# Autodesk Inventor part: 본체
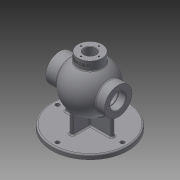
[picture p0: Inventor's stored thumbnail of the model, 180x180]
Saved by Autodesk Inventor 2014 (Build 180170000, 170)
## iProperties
Created: 2020-08
Part Number: 본체
Material: Generic
Document SubType Name: Modeling
Designer: kh
Density: 1 g/cm^3
Appearance: Default
Author: kh
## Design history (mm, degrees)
sketch "Sketch1"
  geometry: C1 r 85 at (0, 0); 1 further point
  constraints: 1 centre point, 1 coincident
  dimensions: "d0" = 170 diameter of C1
extrude "Extrusion1" new body sketch "Sketch1" distance "d1" = 10; taper "d2" = 0 deg
sketch "Sketch2"
  geometry: L1 (85, 10)-(-85, 10) reference; L2 (-85, 0)-(85, 0) reference; L3 (0, 0)-(0, 137.595); L4 (54.192, 85)-(43, 85); L5 (53, 85)-(43, 85); L6 (-43, 85)-(-53, 85); L7 (43, 85)-(-43, 85); A1 r 53 centre (0, 85) between (53, 85) and (-53, 85); A2 r 43 centre (0, 85) between (43, 85) and (-43, 85); 1 further point
  constraints: 10 end point, 4 collinear, 4 point on circle, 2 centre point, 2 coincident, 2 parallel, 2 point on line, 1 midpoint, 1 perpendicular
  dimensions: "d5" = 53 radius of A1; "d7" = 85 distance between parallel lines of L2 L7; "d8" = 43 radius of A2
revolve "Revolution1" sketch "Sketch2" stored, may be unused: angle "d9" = 90 deg
workplane "Work Plane1"
sketch "Sketch3"
  geometry: L1 (85, 10)-(-85, 10) reference; L2 (-85, 0)-(85, 0) reference; L3 (0, 0)-(0, 115.121); C1 r 31 at (0, 85)
  constraints: 2 end point, 1 centre point, 1 perpendicular, 1 point on line
  dimensions: "d11" = 62 diameter of C1; "d12" = 85 distance from line of L2 C1.centre
extrude "Extrusion2" join sketch "Sketch3" stored distance "d13" = 10; taper "d14" = 0 deg
workplane "Work Plane2"
sketch "Sketch4"
  geometry: L1 (0, 0)-(0, 109.575); L2 (-85, 0)-(85, 0) reference; C1 r 31 at (0, 85)
  constraints: 2 end point, 1 centre point, 1 point on line, 1 vertical
  dimensions: "d16" = 62 diameter of C1; "d17" = 85 distance from line of L2 C1.centre
extrude "Extrusion3" join sketch "Sketch4" stored distance "d18" = 10; taper "d19" = 0 deg
workplane "Work Plane3"
sketch "Sketch6"
  geometry: C1 r 27 at (0, 0); 1 further point
  constraints: 1 centre point, 1 coincident
  dimensions: "d24" = 54 diameter of C1
extrude "Extrusion5" join sketch "Sketch6" stored distance "d25" = 10; taper "d26" = 0 deg
sketch "Sketch12"
  geometry: L1 (-52, 4)-(52, 4); L2 (52, 4)-(52, -4); L3 (52, -4)-(-52, -4); L4 (-52, -4)-(-52, 4); L5 (0, 4)-(0, -4); 3 further points
  constraints: 10 end point, 4 midpoint, 2 parallel, 2 perpendicular, 1 coincident, 1 horizontal, 1 horizontal alignment, 1 other
  dimensions: "d36" = 104 distance of L1.start L1.end; "d37" = 8 distance of L1.end L2.end
extrude "Extrusion9" join sketch "Sketch12" stored distance "d38" = 1.75; taper "d39" = 0 deg
sketch "Sketch17"
  geometry: L1 (85, 10)-(-85, 10) reference; L2 (-43, 10)-(-43, 39.933); L3 (43, 10)-(43, 41.466); L4 (0, 0)-(0, 61.704)
  constraints: 6 end point, 2 parallel, 2 point on line, 1 perpendicular
  dimensions: "d44" = 43 distance from line of L2 L4.start; "d45" = 43 distance from line of L3 L4.start
feature "Rib1" dims "d46" = 1, "d47" = 8, "d48" = 0, "d49" = 0, "d50" = 1, "d51" = 1
feature "Rib2" dims "d52" = 1, "d53" = 8, "d54" = 0, "d55" = 0, "d56" = 1, "d57" = 1
sketch "Sketch18"
  geometry: C1 r 27 at (0, 0) reference; 1 further point
hole "Hole1" sketch "Sketch18" at (0, 0) diameter "d58" = 26; stored, may be unused: countersink angle "d62" = 90 deg, drill point angle "d64" = 0 deg; dims "d59" = 6, "d60" = 4, "d61" = 2, "d63" = 50
sketch "Sketch19" dims "d65" = 48
  geometry: L1 (0, 0)-(-24, 0); C1 r 31 at (0, 0) reference; 1 further point
  constraints: 2 end point, 1 coincident, 1 horizontal, 1 horizontal alignment, 2 other
hole "Hole2" sketch "Sketch19" at (-24, 0) diameter "d66" = 3.242; stored, may be unused: countersink angle "d70" = 90 deg, drill point angle "d72" = 118 deg; dims "d67" = 12, "d68" = 4, "d69" = 2, "d71" = 15
pattern_circular "Circular Pattern1" dims angle "d74" = 360 deg
sketch "Sketch20" dims "d76" = 48
  geometry: L1 (0, 0)-(24, 0); A1 r 31 centre (0, 0) between (-30.741, -4) and (-30.741, 4) reference; 1 further point
  constraints: 2 end point, 1 coincident, 1 horizontal, 1 horizontal alignment, 2 other
hole "Hole3" sketch "Sketch20" at (24, 0) diameter "d77" = 3.242; stored, may be unused: countersink angle "d81" = 90 deg, drill point angle "d83" = 118 deg; dims "d78" = 12, "d79" = 4, "d80" = 2, "d82" = 15
pattern_circular "Circular Pattern2" dims angle "d85" = 360 deg
sketch "Sketch21" dims "d87" = 40
  geometry: L1 (0, 0)-(0, 20); C1 r 27 at (0, 0) reference; 1 further point
  constraints: 2 end point, 1 coincident, 1 vertical, 1 vertical alignment, 2 other
hole "Hole4" sketch "Sketch21" at (0, 20) diameter "d88" = 3.242; stored, may be unused: countersink angle "d92" = 90 deg, drill point angle "d94" = 118 deg; dims "d89" = 12, "d90" = 4, "d91" = 2, "d93" = 15
pattern_circular "Circular Pattern3" dims angle "d96" = 360 deg
sketch "Sketch22"
  geometry: L1 (-72.5, 0)-(72.5, 0); L2 (0, -72.5)-(0, 72.5); C1 r 85 at (0, 0) reference; A1 r 72.5 centre (0, 0) between (-72.5, 0) and (72.5, 0); 2 further points
  constraints: 4 end point, 4 point on circle, 2 midpoint, 1 centre point, 1 coincident, 1 horizontal, 1 perpendicular
  dimensions: "d98" = 145 diameter of A1
hole "Hole5" sketch "Sketch22" at (-72.5, 0), (0, -72.5), (72.5, 0), (0, 72.5) diameter "d99" = 9; stored, may be unused: countersink angle "d103" = 90 deg, drill point angle "d105" = 0 deg; dims "d100" = 12, "d101" = 4, "d102" = 2, "d104" = 15
chamfer "Chamfer2" distance "d109" = 1; stored, may be unused: second distance "d110" = 2, angle "d111" = 45 deg
fillet "Fillet1" dims "d115" = 3
fillet "Fillet2" dims "d116" = 3
fillet "Fillet3" dims "d117" = 3
fillet "Fillet4" dims "d118" = 3
fillet "Fillet5" dims "d119" = 3
workplane "Work Plane4"
sketch "Sketch23"
  geometry: L1 (-27, 0)-(27, 0) reference; L2 (-27, -17.714)-(27, -17.714) reference; L3 (-27, 0)-(-27, -17.714) reference; L4 (27, 0)-(27, -17.714) reference; L5 (-20.739, -5.998)-(20.739, -5.998); L6 (20.739, -5.998)-(20.739, -12.002); L7 (20.739, -12.002)-(-20.739, -12.002); L8 (-20.739, -12.002)-(-20.739, -5.998); L9 (-20.739, -5.998)-(20.739, -12.002); 2 further points
  constraints: 2 end point, 1 midpoint, 2 other
  dimensions: "d120" = 27 distance from line of point (0, -9) L3; "d121" = 9 distance from line of point (0, -9) L1
emboss "Emboss1" sketch "Sketch23" dims "d0" = 170, "d122" = 0.5, "d123" = 0
sketch "Sketch25"
  geometry: C1 r 1.621 at (0, -24) reference; C2 r 1.621 at (24, 0) reference; C3 r 1.621 at (0, 24) reference; C4 r 1.621 at (-24, 0) reference; C5 r 31 at (0, 0) reference; C6 r 17.5 at (0, 0); 1 further point
  constraints: 1 centre point, 1 coincident
  dimensions: "d124" = 35 diameter of C6
extrude "Extrusion11" cut sketch "Sketch25" distance "d125" = 16; taper "d126" = 0 deg
sketch "Sketch26"
  geometry: C1 r 17.5 at (0, 0) reference; C2 r 18.5 at (0, 0); 1 further point
  constraints: 1 centre point, 1 coincident
  dimensions: "d127" = 37 diameter of C2
extrude "Extrusion12" cut sketch "Sketch26" distance "d128" = 1.75; taper "d129" = 0 deg
sketch "Sketch27"
  geometry: C1 r 18.5 at (0, 0) reference; C2 r 17.5 at (0, 0); 1 further point
  constraints: 1 centre point, 1 coincident
  dimensions: "d130" = 35 diameter of C2
extrude "Extrusion13" cut sketch "Sketch27" stored distance "d131" = 1.75; taper "d132" = 0 deg
chamfer "Chamfer4" distance "d133" = 1; stored, may be unused: second distance "d134" = 2, angle "d135" = 45 deg
chamfer "Chamfer5" distance "d136" = 1; stored, may be unused: second distance "d137" = 2, angle "d138" = 45 deg
body "Solid1"
node "Projected Loop1"
node "Projected Loop2"
node "Projected Loop9"
node "Projected Loop10"
node "Projected Loop11"
node "Projected Loop12"
node "Projected Loop13"
node "Projected Loop14"
node "Projected Loop15"
other parameters: "d3" = 85, "d10" = -68, "d15" = 63
